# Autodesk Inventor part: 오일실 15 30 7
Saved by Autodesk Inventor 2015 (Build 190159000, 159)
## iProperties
Created: 2025-08
Part Number: 오일실 15 30 7
Material: 일반
Document SubType Name: Modeling
Designer: user
Density: 1 g/cm^3
Appearance: 기본값
Author: user
Author: jhkim
Description: 오일-실
Creation Date: 2025-08-05
Sending System: Autodesk Inventor 2026
Preprocessor: ST-DEVELOPER v20.1
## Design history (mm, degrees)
node "오일실 15 30 71"
body "Solid1"
node "기준1"
